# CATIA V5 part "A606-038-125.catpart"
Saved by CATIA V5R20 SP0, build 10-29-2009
Part number: A606-038-125
Source: Unknown
Property "ARTICLENO": "A606-038-125"
Property "BOMINFO": "A606-038-125"
Property "CODE": "A606-038-125"
Property "HOLES": "2"
Property "L": "125.000"
Property "L1": "25.000"
Property "L2": "75.000"
Property "LINA": "A606-038-125"
Property "NB": "A606-038-125"
Property "NBSYN": "$CODE."
Property "NN": "A606"
Property "NT": "Wear Plates, self-lubricating"
Property "SCREW": "2xM6"
Property "SUPPLIER": "CF"
Property "W": "38.000"
Bounding box of the stored display mesh (mm): x -19 to 19, y -5 to 5, z -62.5 to 62.5
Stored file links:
  C:\Users\Utente\Desktop\3D files A606\A606-038-125.catpart
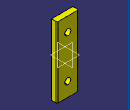
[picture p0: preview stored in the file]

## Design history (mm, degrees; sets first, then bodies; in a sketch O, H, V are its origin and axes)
Body1 "Geometry.1" (main body)
  Solid1 "A606-038-125.catpart": solid without history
